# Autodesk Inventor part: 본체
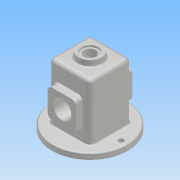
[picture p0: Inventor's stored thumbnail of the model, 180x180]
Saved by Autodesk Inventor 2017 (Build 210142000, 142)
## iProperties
Part Number: 본체
Material: 알루미늄 6061
Document SubType Name: 판금
Designer: user
Density: 2.7 g/cm^3
Sheet Metal Rule: 기본값_mm
Appearance: 알루미늄 - 평지
Mass: 821.705 g
Surface Area: 949.017 cm^2
Volume: 304.335 cm^3
Author: user
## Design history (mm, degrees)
sketch "스케치1"
  geometry: L1 (-37, -37)-(37, -37); L2 (37, -37)-(37, 37); L3 (37, 37)-(-37, 37); L4 (-37, 37)-(-37, -37); L5 (-37, -37)-(37, 37); L6 (37, -37)-(-37, 37); 1 further point
  constraints: 12 end point, 2 midpoint, 2 parallel, 1 horizontal, 1 perpendicular
  dimensions: "d0" = 74 distance of L2.end L3.end; "d1" = 74 distance of L1.end L2.end
extrude "돌출1" new body sketch "스케치1" distance "d2" = 110; taper "d3" = 0 deg
sketch "스케치2"
  geometry: C1 r 67 at (0, 0); 1 further point
  constraints: 1 centre point, 1 coincident
  dimensions: "d4" = 134 diameter of C1
extrude "돌출2" join sketch "스케치2" distance "d5" = 10; taper "d6" = 0 deg
node "작업 평면1"
sketch "스케치3"
  geometry: A1 r 20 centre (0, 0) between (-20, 0) and (20, 0); 1 further point
  constraints: 2 horizontal alignment, 2 point on circle, 1 centre point, 1 coincident
  dimensions: "d8" = 40 diameter of A1
sketch "스케치4"
  geometry: L1 (20, 120)-(23.555, 86.18); L2 (-20, 120)-(-23.153, 90); L3 (20, 120)-(-20, 120); L4 (-37, 10)-(37, 10) reference; L5 (37, 10)-(37, 110) reference; L6 (-37, 110)-(37, 110) reference; L7 (-37, 10)-(-37, 110) reference; L8 (-23.153, 90)-(31.164, 90); 3 further points
  constraints: 8 end point, 2 horizontal, 2 point on line, 1 coincident
  dimensions: "d9" = 6 deg angle of L7 L2; "d10" = 6 deg angle of L5 L1; "d11" = 30 distance between parallel lines of L8 L3
  node "투영된 루프1"
node "작업 평면2"
sketch "스케치5"
  geometry: 4 further points
  constraints: 1 coincident, 1 horizontal alignment, 2 other
feature "로프트1" sketch "스케치5" dims "d13" = 0, "d14" = 90 deg, "d15" = 0, "d16" = 90 deg
sketch "스케치6"
  geometry: L1 (25, 80)-(-25, 80); L2 (-25, 80)-(-25, 30); L3 (-25, 30)-(25, 30); L4 (25, 30)-(25, 80); L5 (25, 80)-(-25, 30); L6 (-25, 80)-(25, 30); 4 further points
  constraints: 12 end point, 4 midpoint, 2 parallel, 1 horizontal, 1 perpendicular, 1 vertical alignment
  dimensions: "d17" = 50 distance of L1.start L1.end; "d18" = 50 distance of L1.end L2.end; "d19" = 55 distance of point (0, 0) point (0, 55)
extrude "돌출3" join sketch "스케치6" stored distance "d20" = 100; taper "d21" = 0 deg
sketch "스케치7"
  geometry: L1 (32, -32)-(-32, -32); L2 (-32, -32)-(-32, 32); L3 (-32, 32)-(32, 32); L4 (32, 32)-(32, -32); L5 (32, -32)-(-32, 32); L6 (-32, -32)-(32, 32); C1 r 67 at (0, 0) reference
  constraints: 12 end point, 2 midpoint, 2 parallel, 1 horizontal, 1 perpendicular
  dimensions: "d22" = 64 distance of L1.end L2.end; "d23" = 64 distance of L2.end L3.end
extrude "돌출4" cut sketch "스케치7" distance "d24" = 105; taper "d25" = 0 deg
sketch "스케치8"
  geometry: L1 (-32, 0)-(-32, 105) reference; L2 (-50, 80)-(-50, 30) reference; L3 (50, 30)-(50, 80) reference; L4 (-50, 55)-(50, 55); L5 (-32, 80)-(-25, 77.452); L6 (-25, 77.452)-(-25, 55); L7 (-32, 80)-(-32, 55); 1 further point
  constraints: 8 end point, 4 point on line, 2 midpoint, 1 perpendicular
  dimensions: "d26" = 110 deg angle of L1 L5; "d27" = 7 distance between parallel lines of L6 L1; "d28" = 50 diameter of L5.start L4
revolve "회전1" sketch "스케치8" stored, may be unused: angle "d29" = 90 deg
sketch "스케치9"
  geometry: L1 (25, 80)-(-25, 80) reference; L2 (-25, 80)-(-25, 30) reference; L3 (-25, 30)-(25, 30) reference; L4 (25, 30)-(25, 80) reference; L5 (-25, 55)-(25, 55); C1 r 16 at (0, 55); 1 further point
  constraints: 3 midpoint, 2 end point, 1 centre point
  dimensions: "d30" = 32 diameter of C1
extrude "돌출5" cut sketch "스케치9" distance "d31" = 189; taper "d32" = 0 deg
hole "구멍1" diameter "d35" = 21; stored, may be unused: countersink angle "d39" = 90 deg, drill point angle "d41" = 118 deg; dims "d33" = 10, "d34" = 10, "d36" = 6, "d37" = 28, "d38" = 4, "d40" = 0.5 (derived)
chamfer "모따기1" distance "d42" = 1; stored, may be unused: second distance "d43" = 2, angle "d44" = 45 deg
fillet "모깎기1" dims "d45" = 3
fillet "모깎기2" dims "d46" = 3
sketch "스케치10"
  geometry: L1 (-17, 38)-(17, 38); L2 (17, 38)-(17, 72); L3 (17, 72)-(-17, 72); L4 (-17, 72)-(-17, 38); L5 (-17, 38)-(17, 72); L6 (17, 38)-(-17, 72); C1 r 17 at (0, 55) reference; 5 further points
  constraints: 12 end point, 4 coincident, 2 midpoint, 2 parallel, 1 horizontal, 1 perpendicular
  dimensions: "d47" = 34 distance of L2.end L3.end; "d48" = 34 distance of L1.end L2.end
hole "구멍2" sketch "스케치10" at (-17, 72), (17, 72), (-17, 38), (17, 38) diameter "d49" = 3.242; stored, may be unused: countersink angle "d53" = 90 deg, drill point angle "d55" = 118 deg; dims "d50" = 8, "d51" = 28, "d52" = 4, "d54" = 10
fillet "모깎기3" dims "d56" = 8
fillet "모깎기4" dims "d57" = 8
fillet "모깎기5" dims "d58" = 8
fillet "모깎기6" dims "d59" = 3
sketch "스케치11"
  geometry: C1 r 64 at (0, 0) reference; A1 r 55 centre (0, 0) between (55, 0) and (-55, 0)
  constraints: 2 horizontal alignment, 2 point on circle, 1 centre point, 1 coincident
  dimensions: "d60" = 110 diameter of A1
hole "구멍3" sketch "스케치11" at (55, 0), (-55, 0) diameter "d61" = 9; stored, may be unused: countersink angle "d65" = 90 deg, drill point angle "d67" = 118 deg; dims "d62" = 8, "d63" = 28, "d64" = 4, "d66" = 10
sketch "스케치12"
  geometry: L1 (49, -18)-(9, -18) reference; 2 further points
  constraints: 1 vertical alignment, 1 other
  dimensions: "d68" = 28 distance from line of point (29, 10) L1
feature "엠보싱1" sketch "스케치12" dims "d8" = 40, "d69" = 0.5, "d70" = 0, "MinimumRemnant" = 1 (derived)
fillet "모깎기7" dims "d71" = 3
node "솔리드1"
mirror "미러1"
mirror "미러2"
node "투영된 루프2"
other parameters: "K계수" = 4.4, "BendRadius" = 0.5 (derived), "BendReliefWidth" = 0.5 (derived), "BendReliefDepth" = 0.25 (derived), "CornerReliefSize" = 2 (derived), "SeamGap" = 0.01, "TransitionRadius" = 0.5 (= BendRadius), "d12" = 90 deg
